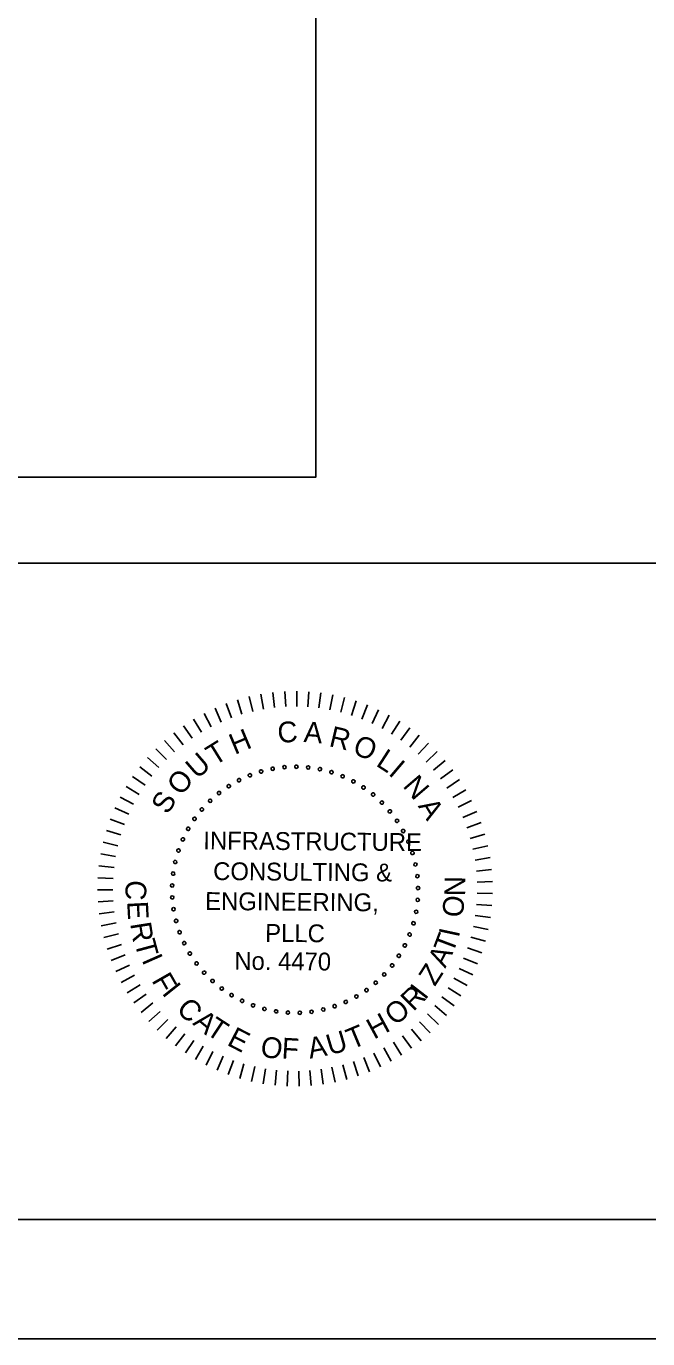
# Model space of a CAD drawing. Extents: x -133.1 to -97, y -1.7 to 20.3.
# Drawn here: x -107.94 to -105.33, y -1.69 to 3.81 of the extents above; entities that cross this region are included whole.
import ezdxf

# ---------------------------------------------------------------- set-up
doc = ezdxf.new("R2010")
doc.units = 0
for name, color, linetype in [('BR_AUTO DIMENSION', 7, 'Continuous'), ('BR_BORDER LINES', 7, 'Continuous'), ('BR_TEXT', 7, 'Continuous'), ('Level 31', 7, 'Continuous')]:
    doc.layers.add(name, color=color, linetype=linetype)

msp = doc.modelspace()

# ---------------------------------------------------------------- linework, layer by layer
at = {"layer": 'BR_AUTO DIMENSION'}
msp.add_lwpolyline([(-124.7207, 1.9196), (-106.7207, 1.9196), (-106.7207, 13.8928), (-124.7207, 13.8928)], close=True, dxfattribs=at)
at = {"layer": 'BR_BORDER LINES'}
for p, q in [((-110.5071, 1.5591), (-105.1419, 1.5591)), ((-131.3076, -1.191), (-97.6416, -1.191))]:
    msp.add_line(p, q, dxfattribs=at)
at = {"layer": 'BR_TEXT'}
for p, q in [((-107.0007, 0.9998), (-106.9858, 0.9379)), ((-106.9512, 1.01), (-106.9401, 0.9473)), ((-106.9012, 1.0172), (-106.894, 0.9539)), ((-106.8509, 1.0213), (-106.8476, 0.9578)), ((-106.8005, 1.0224), (-106.801, 0.9587)), ((-106.75, 1.0204), (-106.7544, 0.9569)), ((-106.6998, 1.0153), (-106.7081, 0.9522)), ((-106.65, 1.0071), (-106.6621, 0.9446)), ((-106.6007, 0.996), (-106.6166, 0.9343)), ((-107.1439, 0.9513), (-107.1181, 0.8932)), ((-107.0972, 0.9704), (-107.0749, 0.9107)), ((-107.0494, 0.9866), (-107.0308, 0.9257)), ((-106.5523, 0.9818), (-106.5719, 0.9213)), ((-106.5048, 0.9648), (-106.528, 0.9055)), ((-106.4584, 0.9448), (-106.4852, 0.8871)), ((-107.2335, 0.9049), (-107.2008, 0.8503)), ((-107.1895, 0.9295), (-107.1601, 0.873)), ((-106.4133, 0.9221), (-106.4436, 0.8661)), ((-106.3697, 0.8967), (-106.4034, 0.8426)), ((-107.3168, 0.8478), (-107.2776, 0.7976)), ((-107.276, 0.8776), (-107.24, 0.8251)), ((-106.3277, 0.8686), (-106.3646, 0.8167)), ((-106.2875, 0.8381), (-106.3275, 0.7885)), ((-107.3925, 0.7811), (-107.3475, 0.736)), ((-107.3557, 0.8156), (-107.3135, 0.7679)), ((-106.2493, 0.8051), (-106.2922, 0.7581)), ((-107.4272, 0.7444), (-107.3795, 0.7022)), ((-106.2131, 0.7699), (-106.2588, 0.7256)), ((-106.1791, 0.7326), (-106.2275, 0.6911)), ((-107.4895, 0.665), (-107.437, 0.6289)), ((-107.4595, 0.7056), (-107.4094, 0.6664)), ((-106.1475, 0.6932), (-106.1983, 0.6548)), ((-107.5169, 0.6226), (-107.4623, 0.5897)), ((-106.1184, 0.652), (-106.1714, 0.6167)), ((-106.0918, 0.6091), (-106.1469, 0.5771)), ((-107.5416, 0.5786), (-107.4852, 0.5491)), ((-106.0679, 0.5646), (-106.1248, 0.5361)), ((-107.5637, 0.5332), (-107.5055, 0.5072)), ((-106.0467, 0.5188), (-106.1052, 0.4938)), ((-107.5829, 0.4865), (-107.5233, 0.4641)), ((-106.0283, 0.4718), (-106.0883, 0.4504)), ((-107.6126, 0.3901), (-107.5507, 0.3751)), ((-107.5992, 0.4387), (-107.5384, 0.42)), ((-106.0129, 0.4237), (-106.0741, 0.406)), ((-107.623, 0.3407), (-107.5604, 0.3295)), ((-106.0004, 0.3748), (-106.0625, 0.3608)), ((-107.6304, 0.2907), (-107.5672, 0.2834)), ((-105.9909, 0.3252), (-106.0538, 0.3151)), ((-105.9845, 0.2751), (-106.0479, 0.2689)), ((-107.6348, 0.2404), (-107.5712, 0.237)), ((-105.9811, 0.2247), (-106.0448, 0.2224)), ((-107.636, 0.19), (-107.5723, 0.1904)), ((-105.9809, 0.1743), (-106.0445, 0.1758)), ((-107.6342, 0.1395), (-107.5706, 0.1438)), ((-105.9836, 0.1239), (-106.0471, 0.1292)), ((-107.6293, 0.0893), (-107.5661, 0.0974)), ((-105.9895, 0.0737), (-106.0525, 0.0829)), ((-107.6213, 0.0394), (-107.5588, 0.0514)), ((-107.6103, -0.0099), (-107.5487, 0.0059)), ((-105.9984, 0.024), (-106.0607, 0.0371)), ((-107.5964, -0.0584), (-107.5358, -0.0388)), ((-106.0252, -0.0733), (-106.0855, -0.0527)), ((-106.0103, -0.025), (-106.0717, -0.0082)), ((-107.5795, -0.106), (-107.5202, -0.0828)), ((-106.043, -0.1205), (-106.1019, -0.0963)), ((-107.5597, -0.1524), (-107.5019, -0.1256)), ((-106.0636, -0.1666), (-106.1209, -0.1389)), ((-107.5371, -0.1976), (-107.4811, -0.1673)), ((-107.5119, -0.2413), (-107.4578, -0.2077)), ((-106.087, -0.2113), (-106.1426, -0.1802)), ((-107.484, -0.2834), (-107.4321, -0.2465)), ((-106.1418, -0.2961), (-106.1931, -0.2584)), ((-106.1131, -0.2545), (-106.1667, -0.22)), ((-107.4536, -0.3237), (-107.404, -0.2837)), ((-107.4208, -0.362), (-107.3737, -0.3191)), ((-106.2065, -0.3735), (-106.2529, -0.3299)), ((-106.173, -0.3358), (-106.2219, -0.2951)), ((-107.3857, -0.3983), (-107.3413, -0.3527)), ((-107.3485, -0.4324), (-107.307, -0.3841)), ((-106.2423, -0.4092), (-106.2859, -0.3628)), ((-107.3092, -0.4642), (-107.2708, -0.4135)), ((-106.32, -0.4736), (-106.3576, -0.4222)), ((-106.2801, -0.4426), (-106.3208, -0.3936)), ((-107.2681, -0.4935), (-107.2328, -0.4405)), ((-107.2253, -0.5203), (-107.1933, -0.4652)), ((-107.1809, -0.5444), (-107.1523, -0.4875)), ((-106.4498, -0.5513), (-106.4774, -0.4939)), ((-106.4049, -0.528), (-106.436, -0.4725)), ((-106.3616, -0.5021), (-106.3961, -0.4485)), ((-107.1352, -0.5657), (-107.1101, -0.5072)), ((-107.0882, -0.5842), (-107.0668, -0.5243)), ((-107.0402, -0.5998), (-107.0225, -0.5387)), ((-106.5915, -0.6041), (-106.6083, -0.5427)), ((-106.5432, -0.5894), (-106.5637, -0.5291)), ((-106.4959, -0.5718), (-106.52, -0.5128)), ((-106.9913, -0.6125), (-106.9773, -0.5504)), ((-106.9418, -0.6221), (-106.9316, -0.5593)), ((-106.8918, -0.6288), (-106.8854, -0.5654)), ((-106.8414, -0.6323), (-106.8389, -0.5687)), ((-106.7909, -0.6328), (-106.7923, -0.5691)), ((-106.7405, -0.6302), (-106.7458, -0.5667)), ((-106.6903, -0.6245), (-106.6995, -0.5615)), ((-106.6406, -0.6158), (-106.6536, -0.5535))]:
    msp.add_line(p, q, dxfattribs=at)
for centre, start, end in [((-106.9977, 0.6702), 21.6807, 201.6807), ((-106.9977, 0.6702), 201.6807, 21.6807), ((-106.9506, 0.6862), 16.1422, 196.1422), ((-106.9506, 0.6862), 196.1422, 16.1422), ((-106.9021, 0.6977), 10.6038, 190.6038), ((-106.9021, 0.6977), 190.6038, 10.6038), ((-106.8527, 0.7043), 5.0653, 185.0653), ((-106.8527, 0.7043), 185.0653, 5.0653), ((-106.8029, 0.7062), 359.5268, 179.5268), ((-106.8029, 0.7062), 179.5268, 359.5268), ((-106.7531, 0.7033), 173.9884, 353.9884), ((-106.7531, 0.7033), 353.9884, 173.9884), ((-106.7039, 0.6956), 168.4499, 348.4499), ((-106.7039, 0.6956), 348.4499, 168.4499), ((-106.6557, 0.6832), 162.9114, 342.9114), ((-106.6557, 0.6832), 342.9114, 162.9114), ((-106.6088, 0.6662), 157.373, 337.373), ((-106.6088, 0.6662), 337.373, 157.373), ((-107.0864, 0.6248), 32.7576, 212.7576), ((-107.0864, 0.6248), 212.7576, 32.7576), ((-107.0431, 0.6496), 27.2191, 207.2191), ((-107.0431, 0.6496), 207.2191, 27.2191), ((-106.5639, 0.6447), 151.8345, 331.8345), ((-106.5639, 0.6447), 331.8345, 151.8345), ((-106.5212, 0.619), 146.2961, 326.2961), ((-106.5212, 0.619), 326.2961, 146.2961), ((-107.1646, 0.5633), 43.8345, 223.8345), ((-107.1646, 0.5633), 223.8345, 43.8345), ((-107.127, 0.5959), 38.2961, 218.2961), ((-107.127, 0.5959), 218.2961, 38.2961), ((-106.4811, 0.5893), 140.7576, 320.7576), ((-106.4811, 0.5893), 320.7576, 140.7576), ((-106.4442, 0.5559), 135.2191, 315.2191), ((-106.4442, 0.5559), 315.2191, 135.2191), ((-107.1989, 0.5271), 49.373, 229.373), ((-107.1989, 0.5271), 229.373, 49.373), ((-106.4106, 0.5191), 129.6807, 309.6807), ((-106.4106, 0.5191), 309.6807, 129.6807), ((-107.2563, 0.4458), 60.4499, 240.4499), ((-107.2563, 0.4458), 240.4499, 60.4499), ((-107.2296, 0.4879), 54.9114, 234.9114), ((-107.2296, 0.4879), 234.9114, 54.9114), ((-106.3808, 0.4792), 124.1422, 304.1422), ((-106.3808, 0.4792), 304.1422, 124.1422), ((-106.3549, 0.4366), 118.6038, 298.6038), ((-106.3549, 0.4366), 298.6038, 118.6038), ((-107.2788, 0.4014), 65.9884, 245.9884), ((-107.2788, 0.4014), 245.9884, 65.9884), ((-106.3333, 0.3917), 113.0653, 293.0653), ((-106.3333, 0.3917), 293.0653, 113.0653), ((-107.297, 0.3549), 71.5268, 251.5268), ((-107.297, 0.3549), 251.5268, 71.5268), ((-106.3161, 0.3449), 107.5268, 287.5268), ((-106.3161, 0.3449), 287.5268, 107.5268), ((-107.3106, 0.307), 77.0653, 257.0653), ((-107.3106, 0.307), 257.0653, 77.0653), ((-106.3035, 0.2967), 101.9884, 281.9884), ((-106.3035, 0.2967), 281.9884, 101.9884), ((-107.3195, 0.258), 82.6038, 262.6038), ((-107.3195, 0.258), 262.6038, 82.6038), ((-106.2956, 0.2475), 96.4499, 276.4499), ((-106.2956, 0.2475), 276.4499, 96.4499), ((-107.3236, 0.2083), 88.1422, 268.1422), ((-107.3229, 0.1585), 93.6807, 273.6807), ((-107.3236, 0.2083), 268.1422, 88.1422), ((-107.3229, 0.1585), 273.6807, 93.6807), ((-106.2925, 0.1977), 90.9114, 270.9114), ((-106.2925, 0.1977), 270.9114, 90.9114), ((-107.3174, 0.109), 99.2191, 279.2191), ((-107.3174, 0.109), 279.2191, 99.2191), ((-106.2942, 0.1479), 85.373, 265.373), ((-106.2942, 0.1479), 265.373, 85.373), ((-107.3071, 0.0602), 104.7576, 284.7576), ((-107.3071, 0.0602), 284.7576, 104.7576), ((-106.312, 0.05), 74.2961, 254.2961), ((-106.312, 0.05), 254.2961, 74.2961), ((-106.3007, 0.0985), 79.8345, 259.8345), ((-106.3007, 0.0985), 259.8345, 79.8345), ((-107.2922, 0.0126), 110.2961, 290.2961), ((-107.2922, 0.0126), 290.2961, 110.2961), ((-106.3279, 0.0028), 68.7576, 248.7576), ((-106.3279, 0.0028), 248.7576, 68.7576), ((-107.2728, -0.0332), 115.8345, 295.8345), ((-107.2728, -0.0332), 295.8345, 115.8345), ((-106.3483, -0.0427), 63.2191, 243.2191), ((-106.3483, -0.0427), 243.2191, 63.2191), ((-107.249, -0.077), 121.373, 301.373), ((-107.249, -0.077), 301.373, 121.373), ((-106.3729, -0.086), 57.6807, 237.6807), ((-106.3729, -0.086), 237.6807, 57.6807), ((-107.2211, -0.1183), 126.9114, 306.9114), ((-107.2211, -0.1183), 306.9114, 126.9114), ((-107.1894, -0.1567), 132.4499, 312.4499), ((-107.1894, -0.1567), 312.4499, 132.4499), ((-106.4342, -0.1645), 46.6038, 226.6038), ((-106.4342, -0.1645), 226.6038, 46.6038), ((-106.4016, -0.1267), 52.1422, 232.1422), ((-106.4016, -0.1267), 232.1422, 52.1422), ((-107.1541, -0.1919), 137.9884, 317.9884), ((-107.1541, -0.1919), 317.9884, 137.9884), ((-107.1156, -0.2235), 143.5268, 323.5268), ((-107.1156, -0.2235), 323.5268, 143.5268), ((-106.4702, -0.1989), 41.0653, 221.0653), ((-106.4702, -0.1989), 221.0653, 41.0653), ((-107.0742, -0.2512), 149.0653, 329.0653), ((-107.0742, -0.2512), 329.0653, 149.0653), ((-107.0303, -0.2749), 154.6038, 334.6038), ((-107.0303, -0.2749), 334.6038, 154.6038), ((-106.5957, -0.2793), 24.4499, 204.4499), ((-106.5513, -0.2566), 29.9884, 209.9884), ((-106.5513, -0.2566), 209.9884, 29.9884), ((-106.5093, -0.2297), 35.5268, 215.5268), ((-106.5093, -0.2297), 215.5268, 35.5268), ((-106.9843, -0.2941), 160.1422, 340.1422), ((-106.9843, -0.2941), 340.1422, 160.1422), ((-106.9367, -0.3089), 165.6807, 345.6807), ((-106.9367, -0.3089), 345.6807, 165.6807), ((-106.8879, -0.3189), 171.2191, 351.2191), ((-106.8879, -0.3189), 351.2191, 171.2191), ((-106.8384, -0.3242), 356.7576, 176.7576), ((-106.8384, -0.3242), 176.7576, 356.7576), ((-106.7885, -0.3248), 2.2961, 182.2961), ((-106.7885, -0.3248), 182.2961, 2.2961), ((-106.7389, -0.3205), 7.8345, 187.8345), ((-106.7389, -0.3205), 187.8345, 7.8345), ((-106.6899, -0.3114), 13.373, 193.373), ((-106.6899, -0.3114), 193.373, 13.373), ((-106.642, -0.2976), 18.9114, 198.9114), ((-106.642, -0.2976), 198.9114, 18.9114), ((-106.5957, -0.2793), 204.4499, 24.4499)]:
    msp.add_arc(centre, 0.00701, start, end, dxfattribs=at)
at = {"layer": 'Level 31'}
msp.add_lwpolyline([(-133.1409, -1.691), (-97.141, -1.691), (-97.141, 20.309), (-133.1409, 20.309)], close=True, dxfattribs=at)

# ---------------------------------------------------------------- texts
at = {"layer": 'BR_TEXT'}
for s, height, rotation, p in [('C', 0.0872, 4.7281, (-106.8784, 0.8048)), ('A', 0.0872, 355.6981, (-106.7739, 0.8098)), ('H', 0.0872, 22.7882, (-107.0612, 0.7554)), ('R', 0.0872, 346.6681, (-106.6696, 0.7928)), ('O', 0.0872, 337.638, (-106.5719, 0.763)), ('T', 0.0872, 31.8182, (-107.1461, 0.7078)), ('L', 0.0872, 327.108, (-106.4731, 0.7125)), ('U', 0.0872, 40.8482, (-107.2194, 0.6516)), ('I', 0.0872, 319.578, (-106.4205, 0.6747)), ('O', 0.0872, 49.8782, (-107.2864, 0.5806)), ('N', 0.0872, 310.548, (-106.3597, 0.6239)), ('S', 0.0872, 58.9083, (-107.3418, 0.5024)), ('A', 0.0872, 301.5179, (-106.2946, 0.5415)), ('INFRASTRUCTURE', 0.074771, 359.5268, (-107.1932, 0.3599)), ('CONSULTING &', 0.074771, 359.5268, (-107.1519, 0.2313)), ('C', 0.0872, 267.025, (-107.5168, 0.2325)), ('N', 0.0872, 89.2085, (-106.0953, 0.1628)), ('ENGINEERING,', 0.074771, 359.5268, (-107.1855, 0.1059)), ('E', 0.0872, 273.025, (-107.5124, 0.1409)), ('O', 0.0872, 83.2085, (-106.1064, 0.0713)), ('R', 0.0872, 279.025, (-107.4996, 0.0487)), ('PLLC', 0.07477, 359.5268, (-106.9338, -0.0277)), ('T', 0.0872, 69.3954, (-106.1476, -0.0805)), ('I', 0.0872, 77.9093, (-106.1219, -0.013)), ('T', 0.0872, 285.025, (-107.4822, -0.0301)), ('I', 0.0872, 293.7713, (-107.4525, -0.1032)), ('No. 4470', 0.07477, 359.5268, (-107.0633, -0.1446)), ('A', 0.0872, 63.3954, (-106.1784, -0.1408)), ('F', 0.0872, 299.7713, (-107.4113, -0.1893)), ('Z', 0.0872, 57.3954, (-106.2222, -0.2172)), ('I', 0.0872, 308.5268, (-107.3692, -0.2431)), ('R', 0.0872, 44.5268, (-106.3127, -0.3221)), ('I', 0.0872, 52.3339, (-106.2633, -0.2748)), ('C', 0.0872, 314.5268, (-107.3099, -0.3133)), ('O', 0.0872, 38.5268, (-106.3893, -0.3821)), ('A', 0.0872, 320.5268, (-107.2407, -0.3718)), ('H', 0.0872, 28.5268, (-106.4774, -0.4381)), ('T', 0.0872, 326.5268, (-107.1863, -0.4103)), ('T', 0.0872, 22.5268, (-106.5706, -0.4799)), ('E', 0.0872, 332.5268, (-107.0977, -0.4581)), ('O', 0.0872, 350.5268, (-106.9576, -0.507)), ('F', 0.0872, 356.5268, (-106.8661, -0.5161)), ('A', 0.0872, 10.5268, (-106.7462, -0.5177)), ('U', 0.0872, 16.5268, (-106.6623, -0.5042))]:
    msp.add_text(s, height=height, rotation=rotation, dxfattribs=at).set_placement(p)

doc.saveas('drawing.dxf')
